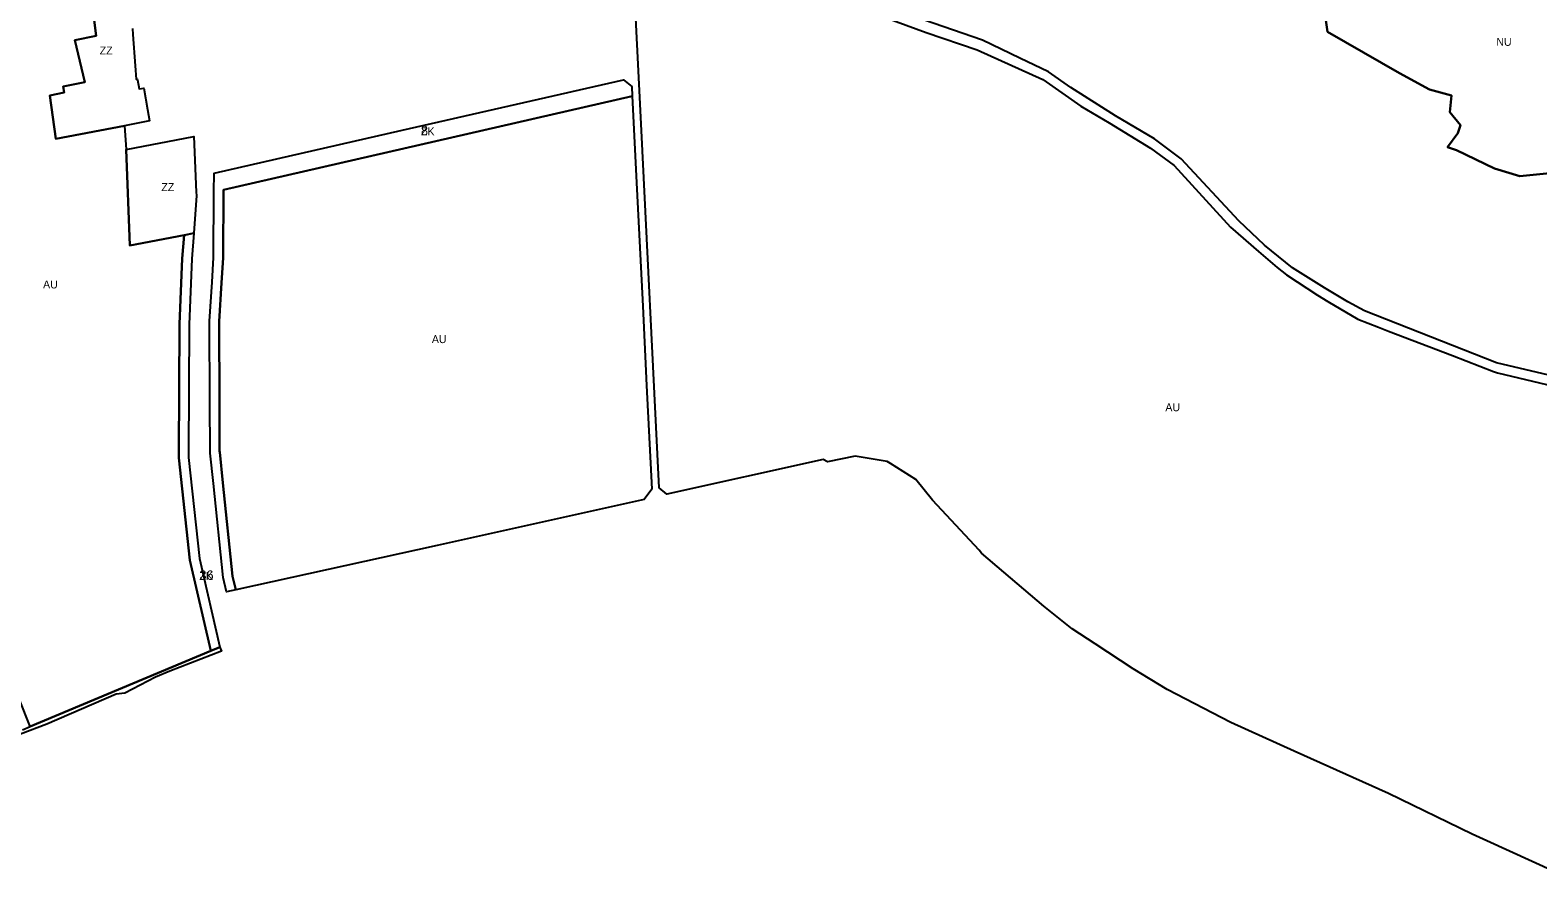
# Model space of a CAD drawing. Extents: x -522079 to -518833, y -1142398 to -1139961.
# Drawn here: x -520390 to -519439, y -1141860 to -1141329 of the extents above; entities that cross this region are included whole.
import ezdxf

# ---------------------------------------------------------------- set-up
doc = ezdxf.new("R2010")
doc.units = 0
for name, color, linetype in [('90640013', 7, 'Continuous'), ('90670013', 7, 'Continuous'), ('90710023', 7, 'Continuous'), ('90730013', 7, 'Continuous'), ('90750013', 7, 'Continuous'), ('90770013', 7, 'Continuous'), ('ID_navrh', 7, 'Continuous')]:
    doc.layers.add(name, color=color, linetype=linetype)

msp = doc.modelspace()

# ---------------------------------------------------------------- linework, layer by layer
at = {"layer": '90640013'}
msp.add_lwpolyline([(-520395.26, -1141770.17), (-520390.37, -1141768.15), (-520276.36, -1141720.39), (-520270.75, -1141718.04), (-520269.8, -1141720.57), (-520302.33, -1141733.12), (-520311.37, -1141736.89), (-520330.69, -1141747.06), (-520336.12, -1141747.68), (-520379.93, -1141766.64), (-520396.49, -1141772.96)], dxfattribs=at)
at = {"layer": '90670013'}
msp.add_lwpolyline([(-520325.78, -1141327.89), (-520325.53, -1141331.62), (-520324.17, -1141351.52), (-520323.6, -1141359.93), (-520322.8, -1141359.78), (-520322.7, -1141360.25), (-520321.57, -1141366.05), (-520318.64, -1141365.48), (-520316.31, -1141378.99), (-520315.07, -1141386.2), (-520330.86, -1141389.2), (-520374.09, -1141397.41), (-520378.01, -1141370.07), (-520368.84, -1141368.35), (-520369.53, -1141364.42), (-520355.94, -1141361.7), (-520362.13, -1141335.31), (-520348.74, -1141332.58), (-520353.1, -1141297.63)], dxfattribs=at)
msp.add_lwpolyline([(-520293.35, -1141458.14), (-520327.5, -1141464.71), (-520329.77, -1141404.14), (-520287.2, -1141396.11), (-520285.62, -1141431.18), (-520285.53, -1141433.12), (-520287.25, -1141456.97)], close=True, dxfattribs=at)
at = {"layer": '90710023'}
for points in [[(-520260.66, -1141681.95), (-520266.52, -1141683.24), (-520268.73, -1141674.23), (-520274.84, -1141614.95), (-520276.82, -1141595.78), (-520276.93, -1141594.74), (-520277.03, -1141563.71), (-520277.2, -1141512.43), (-520275.67, -1141487.93), (-520274.69, -1141472.35), (-520274.48, -1141431.01), (-520274.28, -1141419.2), (-520155.8, -1141392.1), (-520016.19, -1141360.33), (-520010.91, -1141364.55), (-520010.61, -1141370.65), (-520268.47, -1141429.64), (-520268.69, -1141472.55), (-520269.68, -1141488.31), (-520271.2, -1141512.61), (-520271.03, -1141563.69), (-520270.93, -1141594.41), (-520270.85, -1141595.16), (-520268.87, -1141614.33), (-520262.8, -1141673.2), (-520260.68, -1141681.85)], [(-520293.35, -1141458.14), (-520287.25, -1141456.97), (-520288.42, -1141473.23), (-520290.19, -1141514.57), (-520290.52, -1141595.71), (-520290.53, -1141598.43), (-520283.67, -1141662.22), (-520270.75, -1141718.04), (-520276.36, -1141720.39), (-520289.6, -1141663.22), (-520296.53, -1141598.74), (-520296.52, -1141595.69), (-520296.19, -1141514.43), (-520294.41, -1141472.89)]]:
    msp.add_lwpolyline(points, close=True, dxfattribs=at)
at = {"layer": '90730013'}
msp.add_lwpolyline([(-519402.53, -1141416.1), (-519450.75, -1141420.94), (-519466.91, -1141416.21), (-519490.7, -1141404.57), (-519496.45, -1141402.69), (-519489.99, -1141393.96), (-519488.36, -1141388.76), (-519494.92, -1141380.6), (-519493.9, -1141370.24), (-519507.9, -1141366.28), (-519526.67, -1141356.01), (-519572.25, -1141330.06), (-519574.58, -1141312.28)], dxfattribs=at)
at = {"layer": '90750013'}
for points in [[(-519428.71, -1141859.77), (-519471.59, -1141840.28), (-519480.84, -1141836.08), (-519533.59, -1141810.27), (-519593.13, -1141783.65), (-519633.06, -1141765.56), (-519673.22, -1141744.78), (-519694.8, -1141731.79), (-519718.63, -1141715.98), (-519733.23, -1141706.57), (-519747.91, -1141694.83), (-519751.14, -1141692.22), (-519776.39, -1141670.73), (-519790.37, -1141658.77), (-519791.74, -1141656.89), (-519821.3, -1141625.26), (-519831.88, -1141612.23), (-519847.75, -1141602.33), (-519849.83, -1141601.06), (-519870.13, -1141597.7), (-519887.54, -1141601.15), (-519890.16, -1141599.67), (-519988.83, -1141621.62), (-519993.67, -1141617.6), (-520005.29, -1141383.92), (-520010.89, -1141271.2)], [(-520353.1, -1141297.63), (-520348.74, -1141332.58), (-520362.13, -1141335.31), (-520355.94, -1141361.7), (-520369.53, -1141364.42), (-520368.84, -1141368.35), (-520378.01, -1141370.07), (-520374.09, -1141397.41), (-520330.86, -1141389.2), (-520329.77, -1141404.14), (-520327.5, -1141464.71), (-520293.35, -1141458.14), (-520294.41, -1141472.89), (-520296.19, -1141514.43), (-520296.52, -1141595.69), (-520296.53, -1141598.74), (-520289.6, -1141663.22), (-520276.36, -1141720.39), (-520390.37, -1141768.15), (-520417.08, -1141701.53)], [(-519865.42, -1141315.8), (-519825.24, -1141330.38), (-519793.08, -1141341.43), (-519751.63, -1141360.04), (-519727.64, -1141376.95), (-519709.78, -1141387.41), (-519683.78, -1141403.39), (-519668.96, -1141414.21), (-519633.24, -1141453.23), (-519615.77, -1141468.45), (-519603.81, -1141478.65), (-519598.08, -1141483.22), (-519578.53, -1141496.09), (-519571.87, -1141500.11), (-519553.06, -1141511.15), (-519539.97, -1141516.35), (-519536.79, -1141517.61), (-519533.7, -1141518.85), (-519493.41, -1141534.2), (-519467.42, -1141544.19), (-519464.89, -1141545.09), (-519397.82, -1141561.07)]]:
    msp.add_lwpolyline(points, dxfattribs=at)
msp.add_lwpolyline([(-520260.66, -1141681.95), (-520260.68, -1141681.85), (-520262.8, -1141673.2), (-520268.87, -1141614.33), (-520270.85, -1141595.16), (-520270.93, -1141594.41), (-520271.03, -1141563.69), (-520271.2, -1141512.61), (-520269.68, -1141488.31), (-520268.69, -1141472.55), (-520268.47, -1141429.64), (-520010.61, -1141370.65), (-520007.71, -1141429.14), (-520004.05, -1141503.1), (-520002.49, -1141534.74), (-520001.59, -1141552.99), (-519998.35, -1141618.37), (-520003.08, -1141624.98), (-520133.69, -1141653.91)], close=True, dxfattribs=at)
at = {"layer": '90770013'}
for points in [[(-519393.2, -1141555.81), (-519465.6, -1141538.79), (-519548.85, -1141506.03), (-519559.27, -1141500.34), (-519574.1, -1141491.51), (-519594.12, -1141478.91), (-519611.87, -1141464.55), (-519628.16, -1141449.15), (-519664.49, -1141410.15), (-519681.23, -1141397.53), (-519705.92, -1141383), (-519733.94, -1141365.09), (-519748.09, -1141355.2), (-519766.26, -1141346.58), (-519789.84, -1141335.36), (-519864.09, -1141309.46)], [(-519574.58, -1141312.28), (-519572.25, -1141330.06), (-519526.67, -1141356.01), (-519507.9, -1141366.28), (-519493.9, -1141370.24), (-519494.92, -1141380.6), (-519488.36, -1141388.76), (-519489.99, -1141393.96), (-519496.45, -1141402.69), (-519490.7, -1141404.57), (-519466.91, -1141416.21), (-519450.75, -1141420.94), (-519402.53, -1141416.1)]]:
    msp.add_lwpolyline(points, dxfattribs=at)

# ---------------------------------------------------------------- texts
at = {"layer": '90670013'}
for p in [(-520346.54, -1141344.287), (-520307.65, -1141430.429)]:
    msp.add_text('ZZ', height=5, rotation=360, dxfattribs=at).set_placement(p)
at = {"layer": '90710023'}
for rotation, p in [(0, (-520143.905, -1141395.268)), (360, (-520283.64, -1141675.652))]:
    msp.add_text('ZK', height=5, rotation=rotation, dxfattribs=at).set_placement(p)
at = {"layer": '90730013'}
msp.add_text('NU', height=5, rotation=360, dxfattribs=at).set_placement((-519465.666, -1141338.815))
at = {"layer": '90750013'}
for p in [(-520382.25, -1141491.828), (-520137.03, -1141526.3), (-519674.431, -1141569.29)]:
    msp.add_text('AU', height=5, rotation=360, dxfattribs=at).set_placement(p)
at = {"layer": 'ID_navrh'}
for s, p in [('8', (-520143.905, -1141395.268)), ('36', (-520283.64, -1141675.652))]:
    msp.add_text(s, height=6, rotation=360, dxfattribs=at).set_placement(p)

doc.saveas('drawing.dxf')
